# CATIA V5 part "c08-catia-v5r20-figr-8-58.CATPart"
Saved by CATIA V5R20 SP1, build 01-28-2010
Part number: Part1
Bounding box of the stored display mesh (mm): x -50.499 to 50.499, y -68.48 to 68.48, z -46 to 50
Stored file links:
  D:\v5_r20\psrt_files_downloaded\c08-catia-v5r20-prt\c08-catia-v5r20-figr-8-58.CATPart
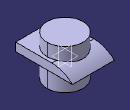
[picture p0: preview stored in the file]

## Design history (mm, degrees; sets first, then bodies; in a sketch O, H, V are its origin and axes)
Body1 (main body)
  Sketch1 on xy-plane, origin (0, 0, 0), H (1, 0, 0), V (0, 1, 0)
    line L1 (-50.499, 68.4797) -> (50.499, 68.4797)
    line L2 (50.499, 68.4797) -> (50.499, -68.4797)
    line L3 (50.499, -68.4797) -> (-50.499, -68.4797)
    line L4 (-50.499, -68.4797) -> (-50.499, 68.4797)
    axis line L5 (50.499, -68.4797) -> (-50.499, 68.4797)
    horizontal: L1 H, L3 H
    vertical: L2 V, L4 V
    midpoint: O L5
  Pad1: profile Sketch1, direction (0, 0, 1), length 20
  Fillet1: radius 71, on edge [face of Pad1 | face of Pad1]
  Body2
    Sketch2 on xy-plane, origin (0, 0, 0), H (1, 0, 0), V (0, 1, 0)
      circle A1 centre (0, 0) radius 43.2524
      point P1 (0, 43.2524)
      coincidence: A1 P1, P1 V
    Pad2: profile Sketch2, direction (0, 0, 1), length 50, opposite side length 46
  Assemble1: tool Body2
